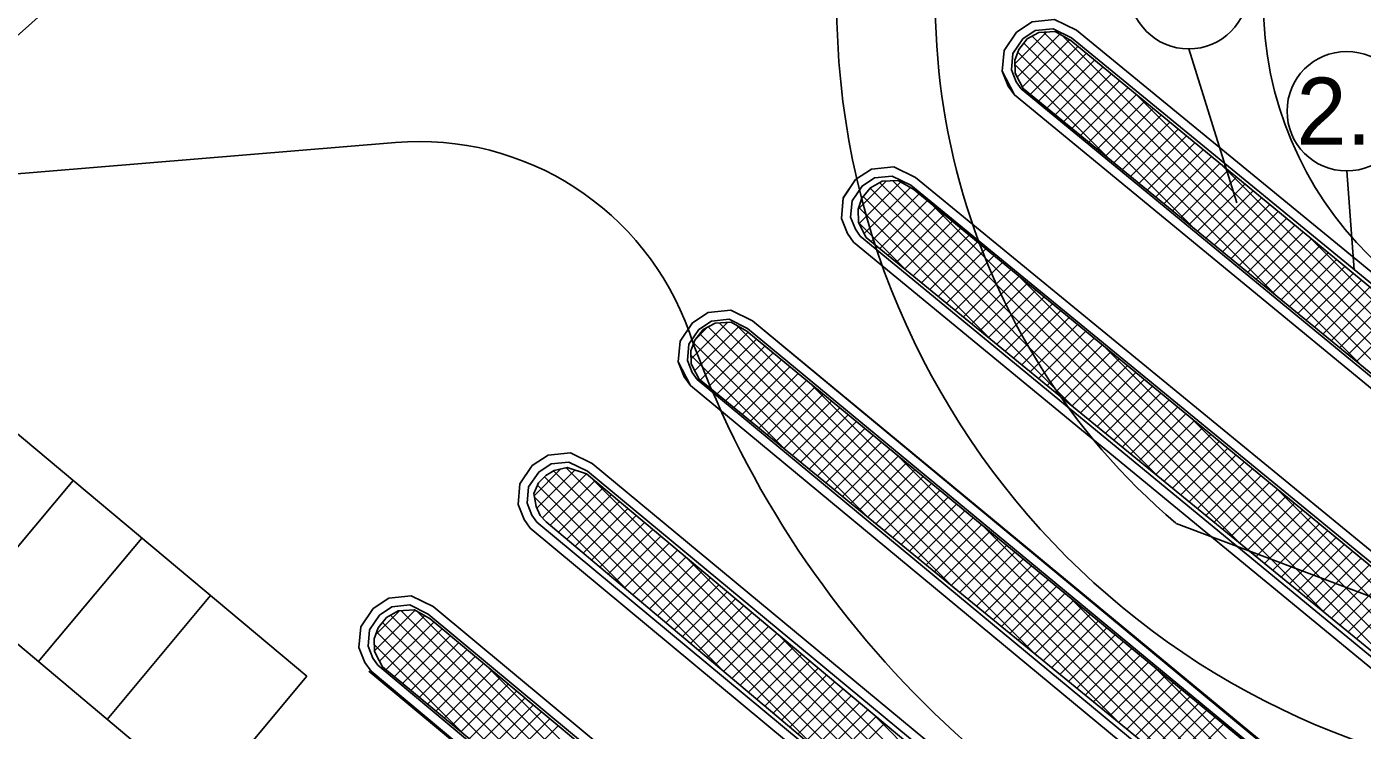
# Model space of a CAD drawing. Extents: x -438410 to -437811, y -1133174 to -1132817.
# Drawn here: x -438102.46 to -438065.2, y -1132972.24 to -1132952.62 of the extents above; entities that cross this region are included whole.
import ezdxf

# ---------------------------------------------------------------- set-up
doc = ezdxf.new("R2010")
doc.units = 0
for name, color, linetype in [('10 - legenda', 7, 'Continuous'), ('Vrstva 1', 7, 'Continuous'), ('Vrstva 5', 7, 'Continuous')]:
    doc.layers.add(name, color=color, linetype=linetype)

msp = doc.modelspace()

# ---------------------------------------------------------------- linework, layer by layer
at = {"layer": '10 - legenda'}
for p, q in [((-438074.891, -1132953.658), (-438074, -1132952.766)), ((-438074.831, -1132954.022), (-438073.64, -1132952.831)), ((-438074.096, -1132952.771), (-438062.879, -1132963.988)), ((-438074.687, -1132954.302), (-438073.371, -1132952.986)), ((-438074.642, -1132953.074), (-438067.548, -1132960.168)), ((-438074.467, -1132954.506), (-438073.134, -1132953.173)), ((-438074.409, -1132952.882), (-438065.213, -1132962.078)), ((-438073.575, -1132952.868), (-438060.544, -1132965.899)), ((-438074.813, -1132953.327), (-438069.882, -1132958.258)), ((-438074.234, -1132954.697), (-438072.901, -1132953.365)), ((-438074.001, -1132954.888), (-438072.669, -1132953.556)), ((-438074.891, -1132953.673), (-438072.217, -1132956.347)), ((-438073.767, -1132955.079), (-438072.436, -1132953.748)), ((-438073.534, -1132955.27), (-438072.204, -1132953.94)), ((-438074.687, -1132954.301), (-438074.551, -1132954.437)), ((-438073.301, -1132955.461), (-438071.971, -1132954.131)), ((-438073.067, -1132955.652), (-438071.738, -1132954.323)), ((-438072.834, -1132955.843), (-438071.506, -1132954.515)), ((-438072.601, -1132956.034), (-438071.273, -1132954.706)), ((-438071.497, -1132954.522), (-438058.21, -1132967.809)), ((-438072.367, -1132956.225), (-438071.041, -1132954.898)), ((-438072.134, -1132956.415), (-438070.808, -1132955.09)), ((-438071.9, -1132956.606), (-438070.575, -1132955.281)), ((-438071.667, -1132956.797), (-438070.343, -1132955.473)), ((-438071.434, -1132956.988), (-438070.11, -1132955.665)), ((-438071.2, -1132957.179), (-438069.877, -1132955.856)), ((-438070.967, -1132957.37), (-438069.645, -1132956.048)), ((-438070.734, -1132957.561), (-438069.412, -1132956.239)), ((-438070.5, -1132957.752), (-438069.18, -1132956.431)), ((-438069.088, -1132956.507), (-438057.563, -1132968.032)), ((-438079.267, -1132957.709), (-438078.481, -1132956.923)), ((-438079.239, -1132958.106), (-438078.078, -1132956.945)), ((-438078.295, -1132956.914), (-438066.243, -1132968.966)), ((-438070.267, -1132957.943), (-438068.947, -1132956.623)), ((-438070.034, -1132958.134), (-438068.714, -1132956.814)), ((-438079.095, -1132958.386), (-438077.809, -1132957.1)), ((-438078.933, -1132957.124), (-438070.912, -1132965.145)), ((-438078.897, -1132958.612), (-438077.563, -1132957.278)), ((-438078.665, -1132956.968), (-438068.577, -1132967.056)), ((-438069.8, -1132958.325), (-438068.482, -1132957.006)), ((-438069.567, -1132958.516), (-438068.249, -1132957.198)), ((-438079.249, -1132957.657), (-438075.581, -1132961.325)), ((-438079.124, -1132957.358), (-438073.246, -1132963.235)), ((-438078.663, -1132958.803), (-438077.331, -1132957.47)), ((-438078.43, -1132958.994), (-438077.098, -1132957.662)), ((-438077.238, -1132957.547), (-438063.908, -1132970.876)), ((-438069.334, -1132958.707), (-438068.017, -1132957.389)), ((-438069.1, -1132958.898), (-438067.784, -1132957.581)), ((-438078.197, -1132959.185), (-438076.866, -1132957.853)), ((-438077.963, -1132959.375), (-438076.633, -1132958.045)), ((-438068.867, -1132959.088), (-438067.551, -1132957.773)), ((-438068.634, -1132959.279), (-438067.319, -1132957.964)), ((-438079.255, -1132958.075), (-438077.916, -1132959.415)), ((-438077.73, -1132959.566), (-438076.4, -1132958.237)), ((-438077.497, -1132959.757), (-438076.168, -1132958.428)), ((-438068.4, -1132959.47), (-438067.086, -1132958.156)), ((-438068.167, -1132959.661), (-438066.853, -1132958.348)), ((-438077.263, -1132959.948), (-438075.935, -1132958.62)), ((-438067.934, -1132959.852), (-438066.621, -1132958.539)), ((-438067.7, -1132960.043), (-438066.388, -1132958.731)), ((-438066.679, -1132958.492), (-438057.213, -1132967.958)), ((-438077.03, -1132960.139), (-438075.703, -1132958.812)), ((-438076.797, -1132960.33), (-438075.47, -1132959.003)), ((-438067.467, -1132960.234), (-438066.156, -1132958.923)), ((-438067.234, -1132960.425), (-438065.923, -1132959.114)), ((-438076.563, -1132960.521), (-438075.237, -1132959.195)), ((-438076.33, -1132960.712), (-438075.005, -1132959.387)), ((-438074.829, -1132959.532), (-438062.306, -1132972.055)), ((-438067, -1132960.616), (-438065.69, -1132959.306)), ((-438066.767, -1132960.807), (-438065.458, -1132959.497)), ((-438076.097, -1132960.903), (-438074.772, -1132959.578)), ((-438075.863, -1132961.094), (-438074.539, -1132959.77)), ((-438066.534, -1132960.998), (-438065.225, -1132959.689)), ((-438066.3, -1132961.189), (-438064.993, -1132959.881)), ((-438075.63, -1132961.285), (-438074.307, -1132959.962)), ((-438075.397, -1132961.476), (-438074.074, -1132960.153)), ((-438066.067, -1132961.38), (-438064.76, -1132960.072)), ((-438065.834, -1132961.571), (-438064.527, -1132960.264)), ((-438075.163, -1132961.667), (-438073.842, -1132960.345)), ((-438074.93, -1132961.858), (-438073.609, -1132960.536)), ((-438065.6, -1132961.761), (-438064.295, -1132960.456)), ((-438065.367, -1132961.952), (-438064.062, -1132960.647)), ((-438083.924, -1132961.882), (-438082.906, -1132960.864)), ((-438083.824, -1132962.207), (-438082.597, -1132960.98)), ((-438083.822, -1132961.356), (-438083.463, -1132960.997)), ((-438083.451, -1132960.991), (-438074.309, -1132970.133)), ((-438083.142, -1132960.876), (-438071.975, -1132972.043)), ((-438082.636, -1132960.958), (-438069.64, -1132973.954)), ((-438074.697, -1132962.048), (-438073.376, -1132960.728)), ((-438074.463, -1132962.239), (-438073.144, -1132960.92)), ((-438083.682, -1132961.184), (-438076.644, -1132968.223)), ((-438083.668, -1132962.475), (-438082.334, -1132961.141)), ((-438083.435, -1132962.666), (-438082.102, -1132961.333)), ((-438074.23, -1132962.43), (-438072.911, -1132961.111)), ((-438073.997, -1132962.621), (-438072.679, -1132961.303)), ((-438083.926, -1132961.789), (-438081.313, -1132964.402)), ((-438083.851, -1132961.44), (-438078.978, -1132966.313)), ((-438083.201, -1132962.857), (-438081.869, -1132961.525)), ((-438082.968, -1132963.048), (-438081.637, -1132961.716)), ((-438073.763, -1132962.812), (-438072.446, -1132961.495)), ((-438073.53, -1132963.003), (-438072.213, -1132961.686)), ((-438072.419, -1132961.517), (-438061.873, -1132972.063)), ((-438082.735, -1132963.239), (-438081.404, -1132961.908)), ((-438082.501, -1132963.43), (-438081.171, -1132962.1)), ((-438073.297, -1132963.194), (-438071.981, -1132961.878)), ((-438073.063, -1132963.385), (-438071.748, -1132962.07)), ((-438083.71, -1132962.429), (-438083.647, -1132962.492)), ((-438082.268, -1132963.621), (-438080.939, -1132962.291)), ((-438082.035, -1132963.812), (-438080.706, -1132962.483)), ((-438072.83, -1132963.576), (-438071.515, -1132962.261)), ((-438072.597, -1132963.767), (-438071.283, -1132962.453)), ((-438081.801, -1132964.002), (-438080.473, -1132962.675)), ((-438081.568, -1132964.193), (-438080.241, -1132962.866)), ((-438080.595, -1132962.575), (-438067.306, -1132975.864)), ((-438072.363, -1132963.958), (-438071.05, -1132962.645)), ((-438072.13, -1132964.149), (-438070.818, -1132962.836)), ((-438081.335, -1132964.384), (-438080.008, -1132963.058)), ((-438081.101, -1132964.575), (-438079.776, -1132963.25)), ((-438071.897, -1132964.34), (-438070.585, -1132963.028)), ((-438071.663, -1132964.531), (-438070.352, -1132963.22)), ((-438080.868, -1132964.766), (-438079.543, -1132963.441)), ((-438080.635, -1132964.957), (-438079.31, -1132963.633)), ((-438071.43, -1132964.721), (-438070.12, -1132963.411)), ((-438071.197, -1132964.912), (-438069.887, -1132963.603)), ((-438070.01, -1132963.501), (-438061.58, -1132971.932)), ((-438080.401, -1132965.148), (-438079.078, -1132963.825)), ((-438080.168, -1132965.339), (-438078.845, -1132964.016)), ((-438070.963, -1132965.103), (-438069.655, -1132963.795)), ((-438070.73, -1132965.294), (-438069.422, -1132963.986)), ((-438079.935, -1132965.53), (-438078.613, -1132964.208)), ((-438070.497, -1132965.485), (-438069.189, -1132964.178)), ((-438070.263, -1132965.676), (-438068.957, -1132964.369)), ((-438079.701, -1132965.721), (-438078.38, -1132964.399)), ((-438079.468, -1132965.912), (-438078.147, -1132964.591)), ((-438078.185, -1132964.56), (-438066.648, -1132976.097)), ((-438070.03, -1132965.867), (-438068.724, -1132964.561)), ((-438069.797, -1132966.058), (-438068.491, -1132964.753)), ((-438088.298, -1132965.697), (-438087.553, -1132964.952)), ((-438088.225, -1132966.048), (-438087.164, -1132964.987)), ((-438088.07, -1132966.318), (-438086.843, -1132965.09)), ((-438087.758, -1132965.001), (-438077.588, -1132975.172)), ((-438087.413, -1132964.922), (-438074.892, -1132977.443)), ((-438079.235, -1132966.103), (-438077.915, -1132964.783)), ((-438079.001, -1132966.294), (-438077.682, -1132964.974)), ((-438069.563, -1132966.249), (-438068.259, -1132964.944)), ((-438069.33, -1132966.44), (-438068.026, -1132965.136)), ((-438088.206, -1132965.402), (-438082.979, -1132970.629)), ((-438088.013, -1132965.171), (-438080.283, -1132972.901)), ((-438087.852, -1132966.524), (-438086.611, -1132965.283)), ((-438087.621, -1132966.718), (-438086.38, -1132965.477)), ((-438086.716, -1132965.196), (-438072.197, -1132979.714)), ((-438078.768, -1132966.485), (-438077.449, -1132965.166)), ((-438078.535, -1132966.676), (-438077.217, -1132965.358)), ((-438069.097, -1132966.631), (-438067.794, -1132965.328)), ((-438067.601, -1132965.486), (-438061.398, -1132971.689)), ((-438088.291, -1132965.742), (-438085.674, -1132968.358)), ((-438087.391, -1132966.912), (-438086.149, -1132965.67)), ((-438087.161, -1132967.106), (-438085.919, -1132965.863)), ((-438078.301, -1132966.866), (-438076.984, -1132965.549)), ((-438078.068, -1132967.057), (-438076.752, -1132965.741)), ((-438068.863, -1132966.822), (-438067.561, -1132965.519)), ((-438068.63, -1132967.013), (-438067.328, -1132965.711)), ((-438086.931, -1132967.3), (-438085.688, -1132966.057)), ((-438086.7, -1132967.494), (-438085.457, -1132966.25)), ((-438077.835, -1132967.248), (-438076.519, -1132965.933)), ((-438077.601, -1132967.439), (-438076.286, -1132966.124)), ((-438068.397, -1132967.204), (-438067.096, -1132965.903)), ((-438068.163, -1132967.394), (-438066.863, -1132966.094)), ((-438086.47, -1132967.688), (-438085.226, -1132966.444)), ((-438077.368, -1132967.63), (-438076.054, -1132966.316)), ((-438077.135, -1132967.821), (-438075.821, -1132966.508)), ((-438075.776, -1132966.545), (-438066.355, -1132975.966)), ((-438067.93, -1132967.585), (-438066.631, -1132966.286)), ((-438067.697, -1132967.776), (-438066.398, -1132966.478)), ((-438086.24, -1132967.882), (-438084.995, -1132966.637)), ((-438086.01, -1132968.076), (-438084.764, -1132966.83)), ((-438076.901, -1132968.012), (-438075.589, -1132966.699)), ((-438076.668, -1132968.203), (-438075.356, -1132966.891)), ((-438067.463, -1132967.967), (-438066.165, -1132966.669)), ((-438067.23, -1132968.158), (-438065.933, -1132966.861)), ((-438085.779, -1132968.27), (-438084.534, -1132967.024)), ((-438085.549, -1132968.464), (-438084.303, -1132967.217)), ((-438076.435, -1132968.394), (-438075.123, -1132967.083)), ((-438076.201, -1132968.585), (-438074.891, -1132967.274)), ((-438066.997, -1132968.349), (-438065.7, -1132967.053)), ((-438066.763, -1132968.54), (-438065.468, -1132967.244)), ((-438085.319, -1132968.658), (-438084.072, -1132967.411)), ((-438085.089, -1132968.852), (-438083.841, -1132967.604)), ((-438084.1, -1132967.387), (-438071.372, -1132980.115)), ((-438075.968, -1132968.776), (-438074.658, -1132967.466)), ((-438075.735, -1132968.967), (-438074.425, -1132967.658)), ((-438066.53, -1132968.731), (-438065.235, -1132967.436)), ((-438066.297, -1132968.922), (-438065.002, -1132967.628)), ((-438084.858, -1132969.046), (-438083.61, -1132967.797)), ((-438084.628, -1132969.24), (-438083.379, -1132967.991)), ((-438075.501, -1132969.158), (-438074.193, -1132967.849)), ((-438075.268, -1132969.349), (-438073.96, -1132968.041)), ((-438066.063, -1132969.113), (-438064.77, -1132967.819)), ((-438065.83, -1132969.304), (-438064.537, -1132968.011)), ((-438084.398, -1132969.434), (-438083.148, -1132968.184)), ((-438084.168, -1132969.628), (-438082.918, -1132968.378)), ((-438075.035, -1132969.539), (-438073.728, -1132968.232)), ((-438074.801, -1132969.73), (-438073.495, -1132968.424)), ((-438065.597, -1132969.495), (-438064.304, -1132968.202)), ((-438065.363, -1132969.686), (-438064.072, -1132968.394)), ((-438083.937, -1132969.822), (-438082.687, -1132968.571)), ((-438083.707, -1132970.016), (-438082.456, -1132968.764)), ((-438074.568, -1132969.921), (-438073.262, -1132968.616)), ((-438074.335, -1132970.112), (-438073.03, -1132968.807)), ((-438073.367, -1132968.529), (-438066.124, -1132975.773)), ((-438092.756, -1132970.024), (-438091.625, -1132968.893)), ((-438092.721, -1132969.565), (-438092.061, -1132968.905)), ((-438092.618, -1132970.311), (-438091.356, -1132969.049)), ((-438092.535, -1132969.232), (-438085.334, -1132976.434)), ((-438092.437, -1132970.554), (-438091.104, -1132969.221)), ((-438092.313, -1132969.03), (-438082.871, -1132978.472)), ((-438092.016, -1132968.903), (-438080.409, -1132980.51)), ((-438091.569, -1132968.925), (-438077.947, -1132982.548)), ((-438083.477, -1132970.21), (-438082.225, -1132968.958)), ((-438083.247, -1132970.404), (-438081.994, -1132969.151)), ((-438074.101, -1132970.303), (-438072.797, -1132968.999)), ((-438073.868, -1132970.494), (-438072.565, -1132969.191)), ((-438092.696, -1132969.495), (-438087.796, -1132974.396)), ((-438092.205, -1132970.746), (-438090.872, -1132969.414)), ((-438091.973, -1132970.938), (-438090.641, -1132969.607)), ((-438083.016, -1132970.598), (-438081.763, -1132969.345)), ((-438082.786, -1132970.792), (-438081.532, -1132969.538)), ((-438081.484, -1132969.579), (-438071.01, -1132980.053)), ((-438073.635, -1132970.685), (-438072.332, -1132969.382)), ((-438073.401, -1132970.876), (-438072.099, -1132969.574)), ((-438092.759, -1132969.857), (-438090.258, -1132972.358)), ((-438091.741, -1132971.131), (-438090.41, -1132969.799)), ((-438082.556, -1132970.986), (-438081.302, -1132969.732)), ((-438082.326, -1132971.18), (-438081.071, -1132969.925)), ((-438073.168, -1132971.067), (-438071.867, -1132969.766)), ((-438072.935, -1132971.258), (-438071.634, -1132969.957)), ((-438091.509, -1132971.323), (-438090.178, -1132969.992)), ((-438091.277, -1132971.515), (-438089.947, -1132970.185)), ((-438082.095, -1132971.374), (-438080.84, -1132970.118)), ((-438081.865, -1132971.568), (-438080.609, -1132970.312)), ((-438072.701, -1132971.449), (-438071.401, -1132970.149)), ((-438072.468, -1132971.64), (-438071.169, -1132970.341)), ((-438091.044, -1132971.707), (-438089.716, -1132970.378)), ((-438090.812, -1132971.899), (-438089.484, -1132970.571)), ((-438089.573, -1132970.497), (-438076.036, -1132984.034)), ((-438081.635, -1132971.762), (-438080.378, -1132970.505)), ((-438081.405, -1132971.956), (-438080.147, -1132970.699)), ((-438072.235, -1132971.831), (-438070.936, -1132970.532)), ((-438072.001, -1132972.022), (-438070.704, -1132970.724)), ((-438070.958, -1132970.514), (-438065.946, -1132975.526)), ((-438090.58, -1132972.091), (-438089.253, -1132970.764)), ((-438090.348, -1132972.283), (-438089.022, -1132970.957)), ((-438081.174, -1132972.15), (-438079.916, -1132970.892)), ((-438080.944, -1132972.344), (-438079.686, -1132971.085)), ((-438071.768, -1132972.212), (-438070.471, -1132970.916)), ((-438090.116, -1132972.475), (-438088.79, -1132971.15)), ((-438089.884, -1132972.668), (-438088.559, -1132971.343)), ((-438080.714, -1132972.538), (-438079.455, -1132971.279)), ((-438080.484, -1132972.732), (-438079.224, -1132971.472)), ((-438071.535, -1132972.403), (-438070.238, -1132971.107)), ((-438071.301, -1132972.594), (-438070.006, -1132971.299)), ((-438089.652, -1132972.86), (-438088.328, -1132971.536)), ((-438089.419, -1132973.052), (-438088.096, -1132971.729)), ((-438080.253, -1132972.926), (-438078.993, -1132971.666)), ((-438078.868, -1132971.771), (-438070.756, -1132979.882)), ((-438071.068, -1132972.785), (-438069.773, -1132971.491)), ((-438070.835, -1132972.976), (-438069.541, -1132971.682)), ((-438089.187, -1132973.244), (-438087.865, -1132971.922)), ((-438088.955, -1132973.436), (-438087.634, -1132972.114)), ((-438080.023, -1132973.12), (-438078.762, -1132971.859)), ((-438079.793, -1132973.314), (-438078.531, -1132972.052)), ((-438070.601, -1132973.167), (-438069.308, -1132971.874)), ((-438070.368, -1132973.358), (-438069.075, -1132972.065))]:
    msp.add_line(p, q, dxfattribs=at)
for points in [[(-438105.174, -1132947.896), (-438095.894, -1132946.782), (-438119.005, -1132967.378)], [(-438058.255, -1132968.222), (-438074.905, -1132954.521), (-438075.246, -1132953.861), (-438075.195, -1132953.283), (-438074.85, -1132952.773), (-438074.41, -1132952.486), (-438073.784, -1132952.418), (-438073.176, -1132952.717), (-438056.752, -1132966.178)], [(-438062.73, -1132972.34), (-438079.39, -1132958.631), (-438079.564, -1132958.389), (-438079.731, -1132957.971), (-438079.687, -1132957.398), (-438079.335, -1132956.883), (-438078.895, -1132956.595), (-438078.269, -1132956.528), (-438077.661, -1132956.827), (-438061.221, -1132970.3)], [(-438067.453, -1132976.278), (-438083.94, -1132962.626), (-438084.281, -1132961.966), (-438084.229, -1132961.388), (-438083.884, -1132960.878), (-438083.445, -1132960.59), (-438082.819, -1132960.523), (-438082.21, -1132960.822), (-438065.881, -1132974.359)], [(-438072.02, -1132980.219), (-438088.41, -1132966.605), (-438088.583, -1132966.363), (-438088.75, -1132965.946), (-438088.699, -1132965.367), (-438088.354, -1132964.858), (-438087.914, -1132964.57), (-438087.288, -1132964.502), (-438086.68, -1132964.802), (-438070.403, -1132978.285)], [(-438076.524, -1132984.243), (-438092.85, -1132970.591), (-438093.022, -1132970.35), (-438093.189, -1132969.932), (-438093.138, -1132969.354), (-438092.793, -1132968.844), (-438092.354, -1132968.557), (-438091.728, -1132968.489), (-438091.119, -1132968.789), (-438074.965, -1132982.221)], [(-438092.912, -1132970.591), (-438076.56, -1132984.213)]]:
    msp.add_lwpolyline(points, dxfattribs=at)
for points in [[(-438073.176, -1132952.717), (-438073.784, -1132952.418), (-438074.41, -1132952.486), (-438074.85, -1132952.773), (-438075.195, -1132953.283), (-438075.246, -1132953.861), (-438075.079, -1132954.279), (-438074.905, -1132954.521), (-438058.255, -1132968.222), (-438057.68, -1132968.43), (-438057.085, -1132968.345), (-438056.658, -1132968.016), (-438056.447, -1132967.73), (-438056.287, -1132967.153), (-438056.391, -1132966.651), (-438056.752, -1132966.178)], [(-438073.312, -1132952.929), (-438073.829, -1132952.674), (-438074.323, -1132952.728), (-438074.671, -1132952.955), (-438074.951, -1132953.369), (-438074.991, -1132953.824), (-438074.858, -1132954.158), (-438074.721, -1132954.349), (-438058.129, -1132968.002), (-438057.653, -1132968.174), (-438057.186, -1132968.107), (-438056.838, -1132967.84), (-438056.676, -1132967.619), (-438056.545, -1132967.145), (-438056.625, -1132966.757), (-438056.933, -1132966.353)], [(-438073.336, -1132953.006), (-438073.771, -1132952.754), (-438074.222, -1132952.777), (-438074.55, -1132952.961), (-438074.787, -1132953.251), (-438074.894, -1132953.556), (-438074.886, -1132953.915), (-438074.756, -1132954.167), (-438074.665, -1132954.344), (-438058.189, -1132967.826), (-438057.747, -1132968.024), (-438057.373, -1132968.039), (-438057.044, -1132967.871), (-438056.815, -1132967.604), (-438056.693, -1132967.253), (-438056.701, -1132966.94), (-438056.831, -1132966.611), (-438057.037, -1132966.436)], [(-438077.661, -1132956.827), (-438078.269, -1132956.528), (-438078.895, -1132956.595), (-438079.335, -1132956.883), (-438079.68, -1132957.392), (-438079.731, -1132957.971), (-438079.564, -1132958.389), (-438079.39, -1132958.631), (-438062.73, -1132972.34), (-438062.14, -1132972.492), (-438061.627, -1132972.368), (-438061.215, -1132972.034), (-438060.994, -1132971.709), (-438060.884, -1132971.265), (-438060.96, -1132970.785), (-438061.221, -1132970.3)], [(-438077.797, -1132957.039), (-438078.314, -1132956.784), (-438078.808, -1132956.837), (-438079.156, -1132957.065), (-438079.436, -1132957.479), (-438079.476, -1132957.933), (-438079.343, -1132958.268), (-438079.206, -1132958.459), (-438062.614, -1132972.112), (-438062.138, -1132972.234), (-438061.741, -1132972.138), (-438061.401, -1132971.863), (-438061.226, -1132971.605), (-438061.139, -1132971.254), (-438061.2, -1132970.867), (-438061.418, -1132970.463)], [(-438077.71, -1132957.158), (-438078.145, -1132956.906), (-438078.595, -1132956.929), (-438078.923, -1132957.112), (-438079.16, -1132957.403), (-438079.267, -1132957.708), (-438079.259, -1132958.067), (-438079.13, -1132958.319), (-438079.039, -1132958.496), (-438062.563, -1132971.977), (-438062.12, -1132972.11), (-438061.823, -1132972.054), (-438061.58, -1132971.932), (-438061.339, -1132971.61), (-438061.243, -1132971.404), (-438061.235, -1132971.091), (-438061.312, -1132970.763), (-438061.41, -1132970.587)], [(-438082.21, -1132960.822), (-438082.819, -1132960.523), (-438083.445, -1132960.59), (-438083.884, -1132960.878), (-438084.229, -1132961.388), (-438084.281, -1132961.966), (-438084.114, -1132962.384), (-438083.94, -1132962.626), (-438067.453, -1132976.278), (-438066.808, -1132976.476), (-438066.299, -1132976.339), (-438065.828, -1132976.036), (-438065.619, -1132975.691), (-438065.526, -1132975.241), (-438065.558, -1132974.775), (-438065.877, -1132974.32)], [(-438082.347, -1132961.034), (-438082.864, -1132960.779), (-438083.358, -1132960.833), (-438083.706, -1132961.06), (-438083.986, -1132961.474), (-438084.026, -1132961.929), (-438083.893, -1132962.263), (-438083.756, -1132962.454), (-438067.332, -1132976.054), (-438066.803, -1132976.216), (-438066.402, -1132976.108), (-438066.012, -1132975.857), (-438065.855, -1132975.598), (-438065.778, -1132975.224), (-438065.803, -1132974.862), (-438066.062, -1132974.491)], [(-438082.371, -1132961.111), (-438082.806, -1132960.859), (-438083.257, -1132960.882), (-438083.585, -1132961.065), (-438083.822, -1132961.356), (-438083.928, -1132961.661), (-438083.921, -1132962.02), (-438083.791, -1132962.272), (-438083.7, -1132962.449), (-438067.224, -1132975.93), (-438066.782, -1132976.129), (-438066.476, -1132976.057), (-438066.175, -1132975.83), (-438065.97, -1132975.599), (-438065.861, -1132975.258), (-438065.874, -1132975.044), (-438065.965, -1132974.774), (-438066.072, -1132974.54)], [(-438086.68, -1132964.802), (-438087.288, -1132964.502), (-438087.914, -1132964.57), (-438088.354, -1132964.858), (-438088.699, -1132965.367), (-438088.75, -1132965.946), (-438088.583, -1132966.363), (-438088.41, -1132966.605), (-438072.02, -1132980.219), (-438071.397, -1132980.456), (-438070.686, -1132980.315), (-438070.286, -1132979.945), (-438070.114, -1132979.627), (-438069.997, -1132979.12), (-438070.098, -1132978.737), (-438070.403, -1132978.285)], [(-438086.816, -1132965.013), (-438087.333, -1132964.759), (-438087.828, -1132964.812), (-438088.175, -1132965.039), (-438088.456, -1132965.454), (-438088.496, -1132965.908), (-438088.362, -1132966.242), (-438088.225, -1132966.433), (-438071.892, -1132980), (-438071.376, -1132980.197), (-438070.804, -1132980.084), (-438070.486, -1132979.79), (-438070.35, -1132979.538), (-438070.254, -1132979.124), (-438070.329, -1132978.841), (-438070.59, -1132978.455)], [(-438086.841, -1132965.091), (-438087.384, -1132964.916), (-438087.743, -1132964.992), (-438087.972, -1132965.13), (-438088.178, -1132965.335), (-438088.308, -1132965.641), (-438088.247, -1132966), (-438088.132, -1132966.252), (-438087.964, -1132966.428), (-438071.965, -1132979.91), (-438071.522, -1132980.109), (-438071.148, -1132980.124), (-438070.819, -1132979.956), (-438070.59, -1132979.689), (-438070.468, -1132979.337), (-438070.476, -1132979.024), (-438070.606, -1132978.696), (-438070.812, -1132978.52)], [(-438091.119, -1132968.789), (-438091.728, -1132968.489), (-438092.354, -1132968.557), (-438092.793, -1132968.844), (-438093.138, -1132969.354), (-438093.189, -1132969.932), (-438093.022, -1132970.35), (-438092.85, -1132970.591), (-438076.524, -1132984.243), (-438075.989, -1132984.423), (-438075.347, -1132984.347), (-438074.898, -1132983.984), (-438074.679, -1132983.645), (-438074.575, -1132983.231), (-438074.635, -1132982.741), (-438074.965, -1132982.221)], [(-438091.256, -1132969), (-438091.773, -1132968.745), (-438092.267, -1132968.799), (-438092.615, -1132969.026), (-438092.895, -1132969.44), (-438092.935, -1132969.895), (-438092.802, -1132970.229), (-438092.665, -1132970.42), (-438076.4, -1132984.021), (-438075.963, -1132984.168), (-438075.448, -1132984.107), (-438075.086, -1132983.815), (-438074.911, -1132983.544), (-438074.829, -1132983.215), (-438074.877, -1132982.828), (-438075.155, -1132982.388)], [(-438091.206, -1132969.136), (-438091.641, -1132968.884), (-438092.091, -1132968.907), (-438092.419, -1132969.09), (-438092.656, -1132969.38), (-438092.763, -1132969.686), (-438092.755, -1132970.045), (-438092.626, -1132970.297), (-438092.535, -1132970.473), (-438076.172, -1132984.016), (-438075.71, -1132984.077), (-438075.418, -1132983.973), (-438075.226, -1132983.798), (-438075.099, -1132983.615), (-438074.99, -1132983.327), (-438074.99, -1132982.995), (-438075.047, -1132982.663), (-438075.16, -1132982.515)]]:
    msp.add_lwpolyline(points, close=True, dxfattribs=at)
for centre in [(-438070.043, -1132951.573), (-438065.636, -1132954.975)]:
    msp.add_circle(centre, 1.666, dxfattribs=at)
at = {"layer": 'Vrstva 1'}
for p, q in [((-438108.146, -1132957.17), (-438092.173, -1132955.846)), ((-438105.183, -1132961.903), (-438094.643, -1132970.733)), ((-438110.419, -1132963.379), (-438094.463, -1132976.746)), ((-438101.159, -1132965.274), (-438104.048, -1132968.724)), ((-438058.229, -1132971.058), (-438070.394, -1132966.474)), ((-438099.242, -1132966.88), (-438102.132, -1132970.329)), ((-438097.326, -1132968.485), (-438100.216, -1132971.935)), ((-438094.643, -1132970.733), (-438097.533, -1132974.182))]:
    msp.add_line(p, q, dxfattribs=at)
for radius in [21.902, 10]:
    msp.add_circle((-438057.962, -1132951.913), radius, dxfattribs=at)
for centre, radius, start, end in [((-438057.961, -1132951.909), 19.15, 161.159, 229.4804), ((-438091.512, -1132963.819), 8, 19.5386, 94.7378), ((-438057.962, -1132951.913), 27.6, 199.5386, 252.4099)]:
    msp.add_arc(centre, radius, start, end, dxfattribs=at)
at = {"layer": 'Vrstva 5'}
for p, q in [((-438070.043, -1132953.239), (-438068.705, -1132957.531)), ((-438065.636, -1132956.641), (-438065.433, -1132959.396))]:
    msp.add_line(p, q, dxfattribs=at)

# ---------------------------------------------------------------- texts
msp.add_text('2.5', height=1.875, dxfattribs=at).set_placement((-438067.037, -1132955.913))

doc.saveas('drawing.dxf')
